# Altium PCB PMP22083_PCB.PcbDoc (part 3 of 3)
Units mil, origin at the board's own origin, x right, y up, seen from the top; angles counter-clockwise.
Board outline 6200 x 4200 mil, 2 copper layers (Top Layer, Bottom Layer), stack 62 mil thick; 186 components, 87 nets, 426 pads, 96 vias.
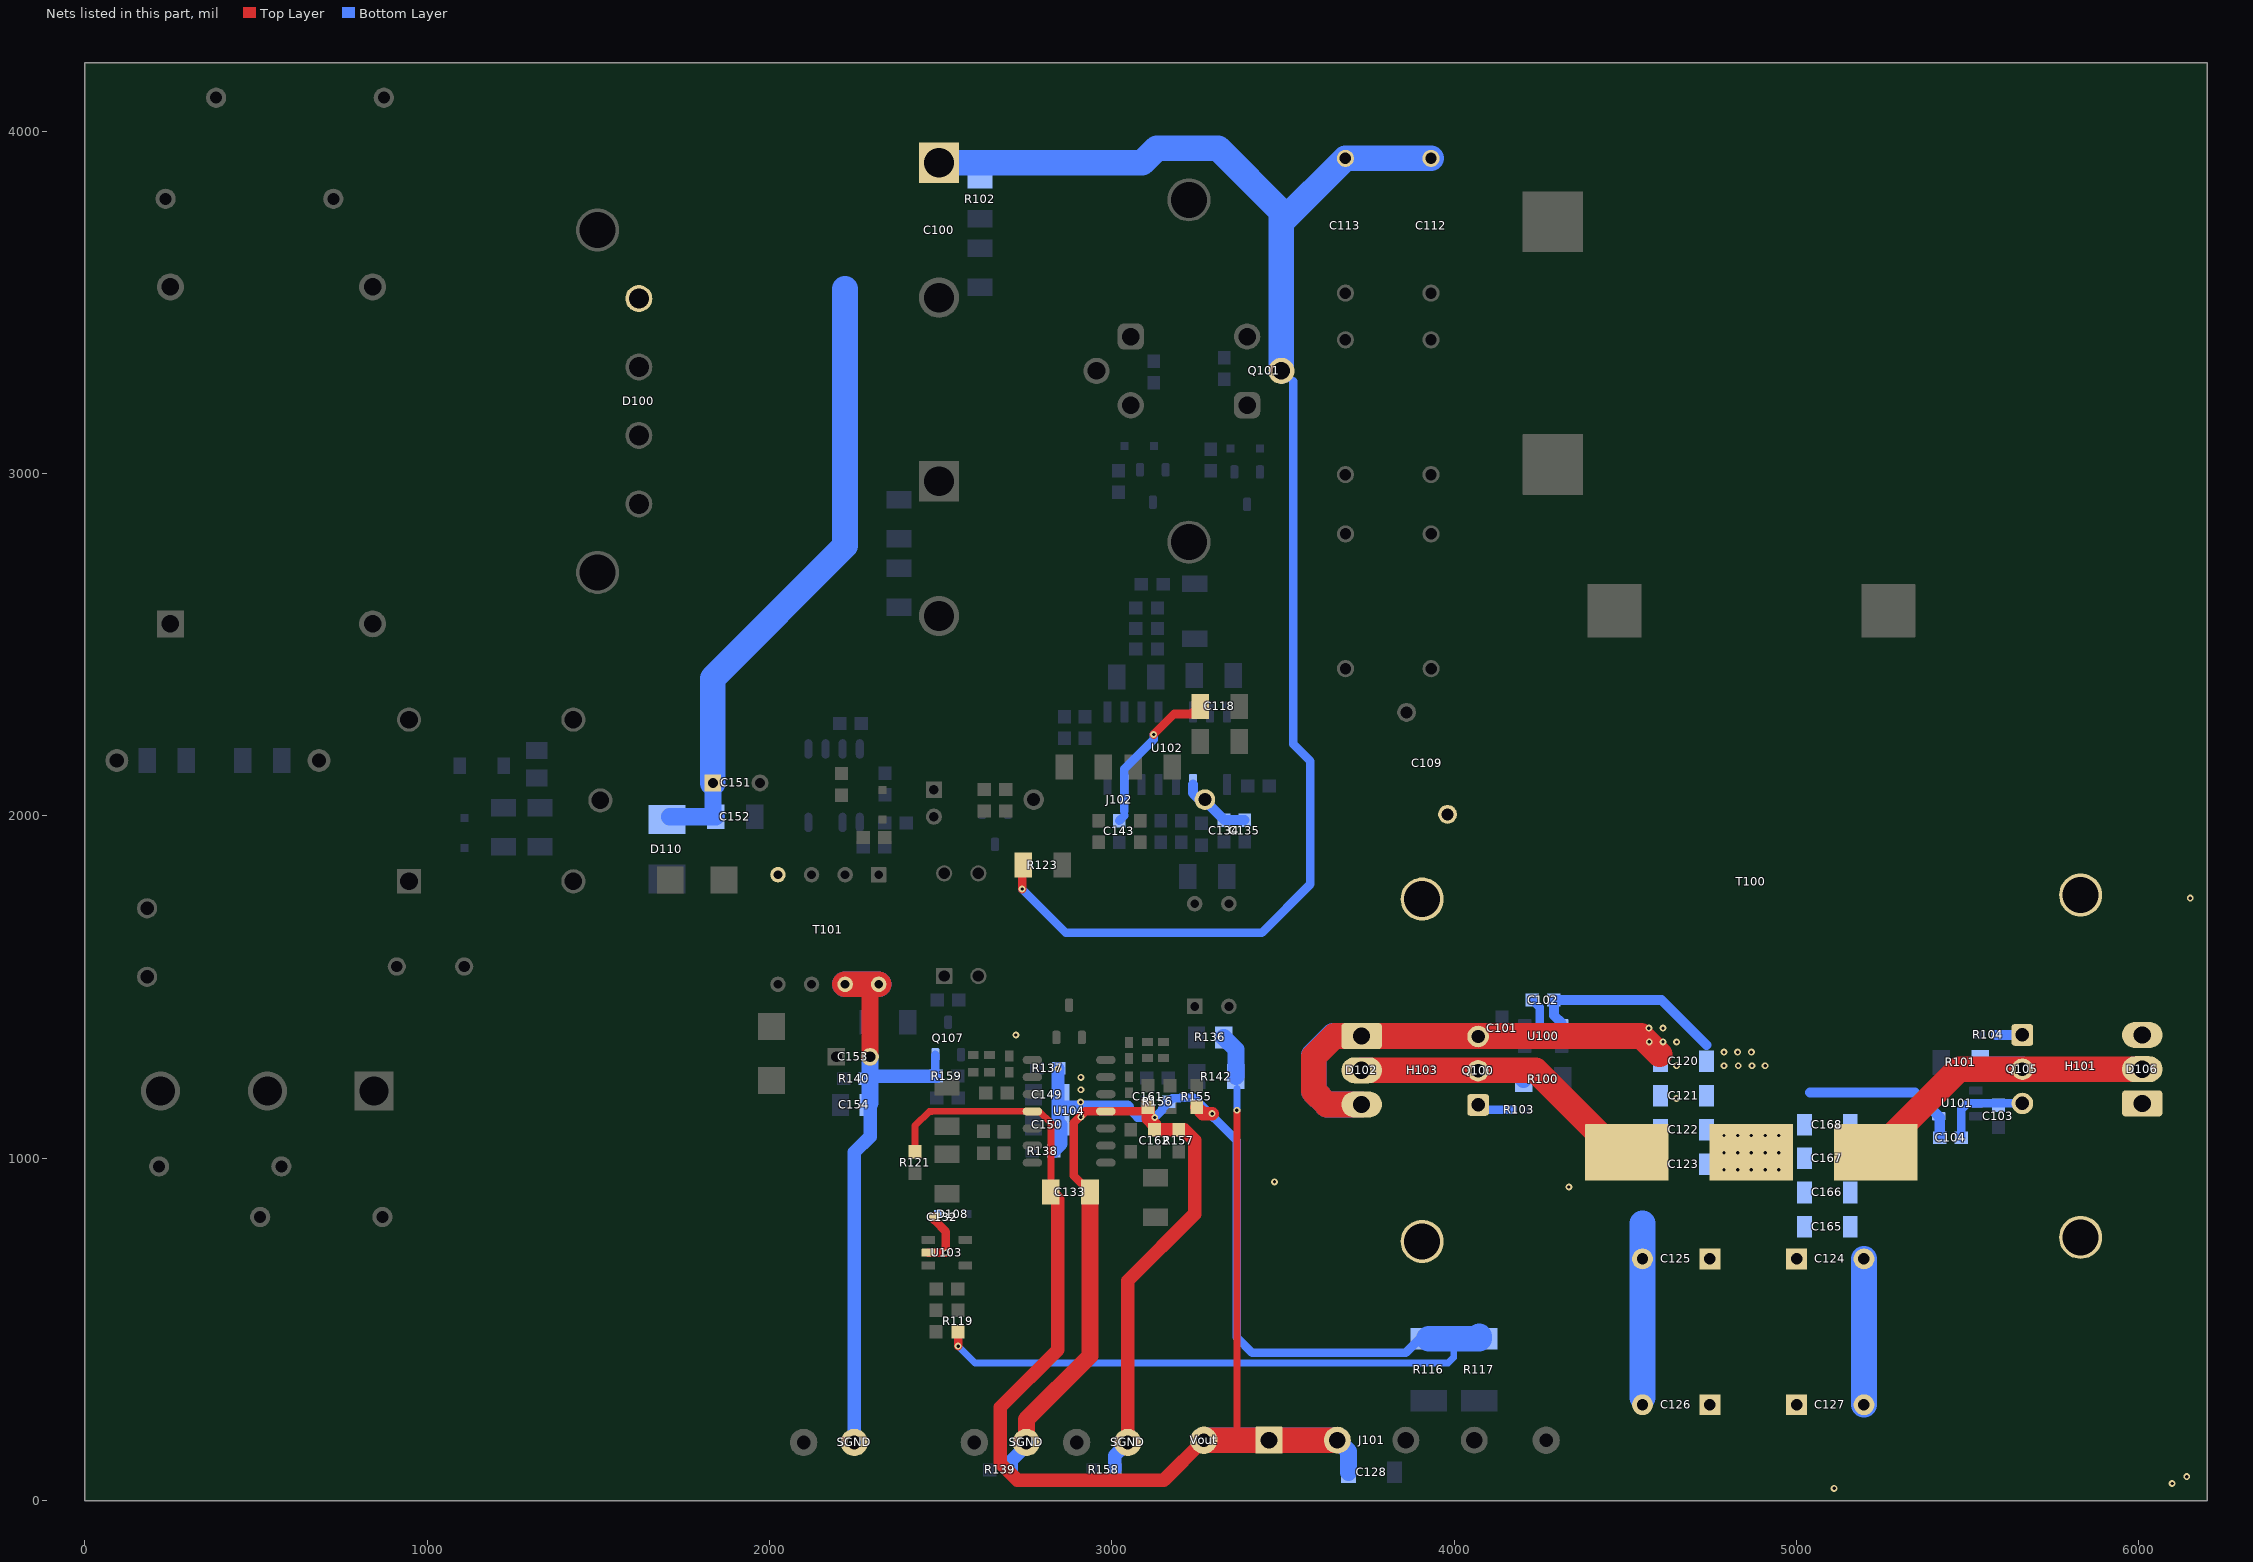
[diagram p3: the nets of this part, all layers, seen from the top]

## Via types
v1: diameter 20, hole 10, Top Layer to Bottom Layer, 96 vias

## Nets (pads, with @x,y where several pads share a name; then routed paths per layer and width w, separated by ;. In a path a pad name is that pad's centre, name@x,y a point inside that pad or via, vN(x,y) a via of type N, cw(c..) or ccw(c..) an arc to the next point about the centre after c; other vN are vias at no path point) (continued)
SGND: C101.2 C102.2 C103.2 C104.2 C109.1 C120.2 C121.2 C122.2 C123.2 C124.2 C125.2 C126.2 C127.2 C132.2 C133.1 C149.2 C150.2 C153.2 C154.2 C161.2 C162.2 C165.1 C166.1 C167.1 C168.1 D102.1 D102.3 D106.1 D106.3 D108.2 H101.1 H101.2 H103.1 H103.2 Q100.3 Q105.3 Q107.2 R116.1 R117.1 R119.2 R137.1 R138.1 R139.1 R140.1 R155.1 R156.1 R157.1 R158.1 R159.1 SGND.1@2248,169.78 SGND.1@2750.42,169.78 SGND.1@3046.72,169.78 T101.7 T101.8 U100.2 U101.2 U103.2 U104.11 | length 11895.4
  Top Layer w25: U103.2@2464.27,724.13 v1(2515.47,724.13) 2515.47,785.55 2481.85,819.17 C132.2@2481.85,828.3 ; v1(2551.22,451.06) R119.2@2551.22,492.95 ; C133.1@2936.41,901.06 2888.34,949.13 2888.34,1102.9 2922.4,1136.96 U104.11@2982.75,1136.96 C161.2@3094.69,1136.96
  Top Layer w39.37: SGND.1@3046.72,169.78 3046.72,641.92 3241.73,836.92 3241.73,1052.72 3211.89,1082.56 R157.1@3195.47,1082.56 C162.2@3124.92,1082.56 3124.92,1097.17 3106.22,1115.87 C161.2@3106.22,1148.49 ; R155.1@3248.38,1148.49 3266.41,1130.45 v1(3292.99,1130.45)
  Top Layer w50: C153.2@2294.17,1296.33 2294.17,1483.22 ; SGND.1@2750.42,169.78 2750.42,236.57 2936.41,422.56 C133.1@2936.41,901.06
  Top Layer w75: T101.7@2221.06,1508.11 T101.8@2319.06,1508.11 ; D102.3@3730,1156.91 3628.53,1156.91 3590,1195.44 3590,1296.91 3650,1356.91 D102.1@3730,1356.91 4546.56,1356.91 4600,1303.48
  Bottom Layer w20: v1(2551.22,451.06) 2600.25,402.04 3982.67,402.04 3998.84,418.21 3998.84,463.17 4008.26,472.59
  Bottom Layer w25: R159.1@2484.74,1242.29 Q107.2@2484.74,1302.76 ; 3045.47,1148.49 3075,1118.96 v1(3125.47,1118.96) 3147.25,1140.74 3147.25,1145.73 R156.1@3166.26,1164.74 3176.43,1174.91 3197.89,1174.91 3199.76,1176.78 3239.76,1176.78 3365.47,1051.06 3365.47,476.57 3410,432.04 3858.84,432.04 R116.1@3899.39,472.59 ; Q100.3@4071.19,1356.78 U100.2@4205.87,1356.78 4206.44,1357.35 4237.19,1357.35 4250,1370.16 4250,1440.46 C102.2@4228.5,1461.96 ; C104.2@5481.5,1060 5481.5,1142.56 5498.94,1160 U101.2@5524.13,1160 Q105.3@5660,1160
  Bottom Layer w39.37: SGND.1@2248,169.78 2248,1017.22 2294.17,1063.39 C154.2@2294.17,1161.82 ; R140.1@2294.17,1240 R159.1@2487.03,1240 ; R139.1@2706.24,89.78 2706.24,116.24 SGND.1@2750.42,160.42 ; R138.1@2830.13,1021.06 2851.49,1042.42 C150.2@2851.49,1097.59 ; C150.2@2842.99,1106.09 v1(2842.99,1261.2) ; 2846.04,1148.49 3045.47,1148.49 ; R158.1@3008.16,90 3008.16,131.22 SGND.1@3046.72,169.78
  Bottom Layer w50: C154.2@2294.17,1161.82 2294.17,1240 C153.2@2294.17,1296.33
  Bottom Layer w75: T101.7@2221.06,1508.11 T101.8@2319.06,1508.11 ; D102.3@3730,1156.91 3628.53,1156.91 3590,1195.44 3590,1300 3646.91,1356.91 D102.1@3730,1356.91 Q100.3@4068.68,1356.91 ; R116.1@3925.58,472.59 4008.26,472.59 R117.1@4073.22,472.59 R117.1@4073.22,479.25 ; C126.2@4550,300 4550,810 ; C127.2@5197.13,280 C124.2@5197.13,706.07
  other v1: 5110,35.58 6097,50 6140,70 4335.39,916.06 3475.37,931.06 2910,1120 2909.11,1163.78 4650,1174.71 2910,1200 2910,1236.26 4650,1270 4570,1340 4610,1340 4650,1339.5 2720,1360 4568.88,1380 4610,1380 6150,1760
Vbus: C100.1 C112.1 C113.1 C151.1 C152.1 D100.1 D110.2 Q101.2 R102.2 R123.2 T101.4 | length 6416.2
  Top Layer w25: v1(2738.22,1786.33) R123.2@2738.22,1853.41
  Bottom Layer w25: T101.4@2025.06,1828.11 T101.4@2027.06,1826.11 ; v1(2738.22,1786.33) 2866.22,1658.32 3438.32,1658.32 3580,1800 3580,2160 3530,2210 3530,3270
  Bottom Layer w50: D110.2@1708.72,1997.49 C152.1@1843.43,1997.49 ; C152.1@1834.69,2006.23 C151.1@1834.69,2096.22
  Bottom Layer w75: C151.1@1834.69,2096.22 1834.69,2402.36 2221.06,2788.73 2221.06,3539.24 ; C100.1@2495.39,3907.57 3089.47,3907.57 3131.81,3949.91 3311.07,3949.91 3495.43,3765.56 3495.43,3733.54 ; Q101.2@3495.43,3299.74 3495.43,3733.54 ; C112.1@3932.48,3920.59 C113.1@3682.48,3920.59 3495.43,3733.54
VCC: C134.2 C135.2 J102.2 U102.3 | length 208.7
  Bottom Layer w29.53: U102.3@3237.08,2091.33 3237.08,2066.33 3255.78,2047.63 3268.41,2047.63 C134.2@3328.22,1987.82 C135.2@3388.22,1987.82
VCR: C118.2 C143.1 U102.7 | length 456.8
  Top Layer w25: v1(3122.08,2237.63) 3182.08,2297.63 3231.68,2297.63 C118.2@3261.68,2327.63
  Bottom Layer w25: C143.1@3022.08,1986.02 C143.1@3037.08,2001.02 ; 3037.08,2014.14 U102.7@3037.08,2091.33 3037.08,2137.63 3122.08,2222.63 v1(3122.08,2237.63)
VD_SR1: D102.2 Q100.2 R100.1 T100.6 | length 920.7
  Top Layer w75: D102.2@3730,1256.91 4237.63,1256.91 T100.6@4428.22,1066.33
  Bottom Layer w50: Q100.2@4070,1255.59 4177.32,1255.59 R100.1@4202.91,1230
VD_SR2: D106.2 Q105.2 R101.1 T100.8 | length 981.8
  Top Layer w75: T100.8@5231.61,1017.35 5474.26,1260 Q105.2@5660,1260 D106.2@6010,1260
  Bottom Layer w75: R101.1@5557.09,1260 Q105.2@5660,1260
VG_SR1: Q100.1 R103.1 | length 81.8
  Bottom Layer w25: Q100.1@4084.53,1141.06 R103.1@4166.38,1141.06
VG_SR2: Q105.1 R104.1 | length 76.4
  Bottom Layer w29.53: R104.1@5583.62,1360 Q105.1@5660,1360
Vout: C102.1 C104.1 C120.1 C121.1 C122.1 C123.1 C124.1 C125.1 C126.1 C127.1 C128.1 C133.2 C165.2 C166.2 C167.2 C168.2 J101.1 J101.2 R121.2 R136.2 R142.2 T100.7 U100.4 U101.4 U104.4 Vout.1 | length 5321
  Top Layer w20: R121.2@2425.47,1018.45 2425.47,1095.47 2466.96,1136.96 2474.08,1136.96 2474.56,1137.44 2768.19,1137.44 U104.4@2768.19,1136.96 2788.19,1136.96 2822.24,1102.9 C133.2@2822.24,901.06 ; 3365.47,180.97 v1(3365.47,1139.94)
  Top Layer w39.37: C133.2@2822.24,901.06 2842.71,880.59 2842.71,440.7 2674.75,272.73 2674.75,108.92 2723.66,60 3152.4,60 Vout.1@3268.84,176.44
  Top Layer w75: Vout.1@3268.84,176.44 J101.1@3458.84,176.44 J101.2@3658.84,176.44
  Bottom Layer w20: v1(3365.47,1139.94) R142.2@3365.47,1203.41
  Bottom Layer w29.53: U100.4@4314.13,1394.18 4291.5,1416.82 C102.1@4291.5,1461.96 4605.8,1461.96 4736.93,1330.83 ; 5040,1192.01 5346.45,1192.01 U101.4@5415.87,1122.6 ; C104.1@5418.5,1060 U101.4@5418.5,1119.96
  Bottom Layer w50: R136.2@3327.08,1352.76 3362.56,1317.28 R142.2@3362.56,1238.23 ; J101.2@3658.84,176.44 3691.91,143.37 C128.1@3691.91,82.62
  Bottom Layer w75: Vout.1@3268.84,176.44 J101.1@3458.84,176.44 J101.2@3658.84,176.44
  other v1: 4788.22,966.33 4828.22,966.33 4868.22,966.33 4908.22,966.33 4948.22,966.33 4788.22,1016.33 4828.22,1016.33 4868.22,1016.33 4908.22,1016.33 4948.22,1016.33 4788.22,1066.33 4828.22,1066.33 4868.22,1066.33 4908.22,1066.33 4948.22,1066.33 4788.22,1270 4830,1270 4870,1270 4908.22,1270 4788.22,1310 4828.22,1310 4868.22,1310

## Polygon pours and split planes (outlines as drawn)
NetC107_2 on Bottom Layer "C107_2" (solid, pour order 134): 60.71,2610 10.71,2560 10.71,1710 40.71,1680 210.71,1680 230.71,1700 230.71,2406.33 300.71,2476.33 300.71,2580.03 270.74,2610
NetC105_2 on Bottom Layer "C105_2" (solid, pour order 132): 110,950 10,1050 10,1550 40,1580 210,1580 230,1560 230,1289.5 280,1239.5 280,996.5 233.5,950
NetC100_2 on Bottom Layer "C100_2" (solid, pour order 124): 810,2511.19 790,2531.19 790,2897.52 1053.67,3161.19 1649.13,3161.19 1669.13,3141.19 1669.13,3082.5 1647.82,3061.19 1471.67,3061.19 921.67,2511.19
NetC111_1 on Bottom Layer "C111_1" (solid, pour order 118): 700,3830 690,3820 690,3790 800,3680 800,3510.02 1050.02,3260 1639.13,3260 1669.13,3290 1669.13,3335.43 1644.56,3360 1479.76,3360 1009.76,3830
NetC107_1 on Bottom Layer "C107_1" (solid, pour order 116): 720,1459.42 720,1460 620,1560 620,2220.14 460,2380.14 460,2698.37 100,3058.37 100,3580 130,3610 290,3610 310,3590 310,3100 610,2800 610,2492.5 752.5,2350 970,2350 1000,2320 1000,2260.03 873.82,2133.84 873.82,1719.44 964.35,1628.91 964.35,1499.58 924.18,1459.42
NetC110_1 on Bottom Layer "C110_1" (solid, pour order 114): 1267.69,1740 1157.11,1850.58 1098.88,1850 897.79,1850 886.85,1839.05 886.85,1722.84 979.69,1630 979.69,1500 779.69,1300 779.69,1139.94 839.69,1079.94 839.69,812.77 859.69,792.77 859.69,790 899.69,790 1267.69,1158
Vout on Bottom Layer "Vout" (solid, pour order 108): 3700,18.96 3720,38.96 3720,291.91 3691.91,320 3321.08,320 3214.17,213.08 3214.17,85.83 3280,20
SGND on Bottom Layer "SGND" (solid, pour order 106): 2752.25,1383.47 2491.51,1383.47 2337.46,1540.37 2200,1540 2190,1530 2190,30.52 2210.52,10 3150,10 3170,30 3170,330 3150,350 2548.18,350 2466.96,431.22 2466.96,461.4 2475.55,470 2566.22,470 2613.66,422.56 3888.46,422.56 3910,444.1 3910,518.2 3888.2,540 3442.08,540 3442.08,1003.41 3194.48,1251.01 3190.87,1254.62 2996.59,1254.62 2964.25,1289.61 2846.12,1289.61
Vout on Bottom Layer "Vout" (solid, pour order 94): 4720,660 4700,680 4700,1319.23 4720,1339.23 4720.15,1339.08 4916.36,1339.08 5070,1185.44 5070,679.2 5050.8,660
SGND on Bottom Layer "SGND" (solid, pour order 102): 5660,2030 5557.09,1927.09 5557.09,1288.56 5435.83,1167.3 4842.2,1167.3 4602.59,1406.91 4289.31,1406.91 4176.22,1520 4176.22,1987.6 4137.5,2030 3845.86,2030 3830,2014.14 3830,1660 3458.84,1288.84 3458.84,492.22 3500,451.06 3848.94,451.06 3880,420 3980,420 4050,350 4308.84,350 4340,318.84 4340,40 4360,20 6160,20 6190,50 6190,1770 5930,2030
PGND on Bottom Layer "Bottom Layer-PGND 1" (solid, pour order 88): 3968.22,3116.33 3998.22,3086.33 3998.22,2987.65 3957.33,2946.76 3921.61,2946.76 3650.86,2946.76 3609.97,2987.65 3609.97,3088.08 3638.22,3116.33
PGND on Bottom Layer "Bottom Layer-PGND" (solid, pour order 86): 3131.55,2717.45 3098.22,2750.78 3098.22,2856.01 3128.22,2886.01 3277.55,2886.01 3304.2,2859.35 3304.2,2751.19 3270.47,2717.45
NetC128_2 on Bottom Layer "C124_2" (solid, pour order 76): 3798.84,62.04 3818.84,42.04 4258.84,42.04 4328.84,112.04 4328.84,317.04 4303.84,342.04 3849.67,342.04 3799.11,291.49
PGND on Bottom Layer "PGND" (solid, pour order 56): 2698.86,2595.7 2689.49,2586.33 2610.53,2586.33 2610.9,2505.95 2581.86,2476.33 2508.22,2476.33 2498.22,2486.33 2456.9,2486.33 2436.9,2506.33 2436.9,2645 2475.14,2683.25 2475.14,2856.33 2560.52,2856.32 2618.22,2914.03 2618.22,3016.33 2618.65,3016.76 2618.65,3390.59 2624.35,3390.59 2701.8,3468.04 2701.8,3609.91 2988.22,3896.33 3278.22,3896.33 3308.22,3866.33 3308.22,3726.33 3218.22,3636.32 2958.22,3636.33 2838.22,3516.33 2838.22,3296.32 2918.22,3216.32 3008.22,3216.33 3038.22,3246.33 3142.54,3246.33 3100.88,3204.67 3100.88,3176.3 3074.44,3150.34 3045.15,3150.34 3045.15,3147.48 2982.13,3084.46 2982.13,2746.87 2929.3,2694.03 2929.3,2636.32 2738.68,2636.32
PGND on Bottom Layer "PGND" (solid, pour order 54): 2508.22,2576.33 2508.22,2231.54 2583.44,2156.33 2611.89,2156.33 2611.89,2104.26 2959.83,1756.33 3373.63,1756.33 3478.22,1860.91 3478.22,2075.95 3448.22,2105.95 3206.15,2105.95 3098.22,2213.88 3098.22,2608.53 3080.42,2626.33 2746.59,2626.33 2696.59,2576.33
NetC112_2 on Bottom Layer "C112_2" (solid, pour order 28): 3668.22,3556.33 3648.22,3536.33 3648.22,3376.33 3668.22,3356.33 3948.53,3356.33 3968.53,3376.33 3968.22,3376.64 3968.22,3536.33 3948.22,3556.33
PGND on Bottom Layer "PGND" (solid, pour order 58): 2488.22,2546.33 2488.22,2046.33 2508.22,2026.33 2508.22,1902.49 2402.06,1796.33 2298.22,1796.33 2298.22,1856.33 2328.22,1856.33 2328.22,1892.76 2171.82,2049.16 2171.82,2137.49 2215.26,2180.93 2262.69,2180.93 2263.98,2179.65 2298.22,2213.89 2298.22,2366.33 2408.22,2476.33 2408.22,2547.57 2399.47,2556.33
PGND on Bottom Layer "PGND" (solid, pour order 44): 1938.22,1966.33 1928.22,1976.33 1928.22,2347.82 2216.72,2636.33 2485.39,2636.33 2498.22,2623.49 2498.22,2575.08 2228.22,2305.08 2228.22,2162.73 2171.82,2106.33 2113.88,2106.33 2018.22,2010.67 2018.22,1976.33 2008.22,1966.33
NetD112_2 on Bottom Layer "D108_2" (solid, pour order 24): 2088.22,1996.33 2098.23,2006.33 2098.23,2007.4 2117.14,2007.4 2128.22,1996.33 2128.22,1946.87 2158.22,1916.87 2158.22,1806.33 2138.22,1786.33 2108.34,1786.33 2088.22,1806.45
Vbus on Bottom Layer "Vbus" (solid, pour order 22): 2058.22,1846.33 2038.22,1866.33 1963.95,1866.33 1867.84,1962.44 1867.84,2036.71 1878.22,2047.09 1878.22,2135.95 1867.84,2146.33 1647.82,2146.33 1628.22,2126.73 1628.22,1956.33 1638.22,1946.33 1740.96,1946.33 1900.96,1786.33 2046.43,1786.33 2058.22,1798.11
Vbus on Bottom Layer "Vbus" (solid, pour order 20): 1588.24,3466.33 1568.24,3486.33 1568.22,3486.33 1568.22,3576.33 2138.22,4146.33 3988.22,4146.33 4018.22,4116.33 4018.22,3916.33 3978.22,3876.33 3828.22,3876.33 3578.22,3626.33 3578.22,3288.57 3545.98,3256.33 3484.49,3256.33 3454.49,3286.33 3454.49,3317.04 3468.22,3330.77 3468.22,3696.33 3278.22,3886.33 3171.24,3886.33 3132.88,3847.97 2569.86,3847.97 2188.22,3466.33
NetD110_1 on Bottom Layer "D110_1" (solid, pour order 90): 1636.28,1898.89 1626.28,1888.89 1626.28,1778.89 1646.28,1758.89 1746.28,1758.89 1756.28,1768.89 1756.28,1890.49 1747.3,1899.47
NetC107_1 on Top Layer "C107_1" (solid, pour order 138): 749.86,2350 620,2220.14 620,1560 720,1460 720,1459.42 924.18,1459.42 964.35,1499.58 964.35,1628.91 873.82,1719.44 873.82,2133.84 1000,2260.03 1000,2320 970,2350
NetC105_2 on Top Layer "C105_2" (solid, pour order 130): 110,950 10,1050 10,1550 40,1580 210,1580 230,1560 230,1289.5 280,1239.5 280,996.5 233.5,950
NetC107_2 on Top Layer "C107_2" (solid, pour order 128): 60,2610 10,2560 10,1710 40,1680 210,1680 230,1700 230,2406.33 300,2476.33 300,2580.03 270.03,2610
PE on Top Layer "PE" (solid, pour order 126): 330,4070 310,4090 310,4170 330,4190 910,4190 930,4170 930,4090 910,4070
NetC100_2 on Top Layer "C100_2" (solid, pour order 122): 810,2510 790,2530 790,2896.33 1053.67,3160 1649.13,3160 1669.13,3140 1669.13,3081.31 1647.82,3060 1471.67,3060 921.67,2510
NetC111_1 on Top Layer "C111_1" (solid, pour order 120): 700,3830 690,3820 690,3790 800,3680 800,3510 1050,3260 1639.13,3260 1669.13,3290 1669.13,3335.43 1644.56,3360 1479.76,3360 1009.76,3830
NetC110_1 on Top Layer "C110_1" (solid, pour order 112): 860,790 860,792.77 840,812.77 840,1079.94 780,1139.94 780,1300 980,1500 980,1630 887.16,1722.84 887.16,2013.11 1010,2135.95 1514.05,2135.95 1540,2110 1540,1991.86 1528.97,1980.83 1330.71,1980.83 1268,1918.12 1268,1158 900,790
SGND on Top Layer "SGND" (solid, pour order 110): 2861.13,1421.05 2898.71,1383.47 2906.72,1383.47 2906.72,1368.69 3084.82,1190.59 3249.9,1194.08 3346.69,1097.29 3346.69,836.78 3330.98,821.06 2859.64,821.06 2832.08,848.62 2832.08,1105.24 2707.33,1230 2262.15,1230 2190,1302.15 2190,1530 2200,1540 2337.83,1540 2456.78,1421.05
SGND on Top Layer "SGND" (solid, pour order 104): 5660,2030 5557.09,1927.09 5557.09,1288.56 5435.83,1167.3 4842.2,1167.3 4602.59,1406.91 4289.31,1406.91 4176.22,1520 4176.22,1987.6 4137.5,2030 3845.86,2030 3830,2014.14 3830,1660 3458.84,1288.84 3458.84,921.16 3960,420 3980,420 4050,350 4308.84,350 4340,318.84 4340,40 4360,20 6160,20 6190,50 6190,1770 5930,2030
VD_SR2 on Top Layer "VD_SR2" (solid, pour order 100): 5120,920 5100,940 5100,1130 5270,1300 5686.96,1300 5700,1286.96 5700,1230 5690,1220 5640,1220 5340,920
VD_SR1 on Top Layer "VD_SR1" (solid, pour order 98): 4010,1220 4000,1230 4000,1282.5 4007.5,1290 4480,1290 4640,1130 4640,940 4620,920 4391.98,920 4091.98,1220
Vout on Top Layer "Vout" (solid, pour order 96): 4679.61,1289.61 4679.61,919.61 4640,880 4218.08,880 3980,640 3715.43,640 3395.43,320 3320.83,320 3310,309.17 3310,30 3320,20 5040,20 5070,50 5070,1160 4890,1340 4730,1340
PGND on Top Layer "PGND" (solid, pour order 52): 2896.27,1819.89 2896.27,1928.88 2888.22,1936.93 2888.22,2045.02 2836.92,2096.33 2671.89,2096.33 2611.89,2156.33 2583.44,2156.33 2508.22,2231.54 2508.22,2576.33 2696.59,2576.33 2746.59,2626.33 3080.42,2626.33 3098.22,2608.53 3098.22,2213.88 3206.15,2105.95 3448.22,2105.95 3478.22,2075.95 3478.22,1860.91 3373.63,1756.33 2959.83,1756.33
PGND on Top Layer "PGND" (solid, pour order 40): 2691.84,2588.54 2689.63,2586.33 2598.22,2586.33 2598.22,2489.11 2581.86,2476.33 2508.22,2476.33 2498.22,2486.33 2548.22,2856.33 2618.22,2926.33 2618.22,3016.33 2618.65,3016.76 2618.65,3806.76 2708.22,3896.33 3278.22,3896.33 3308.22,3866.33 3308.22,3726.33 3278.22,3696.33 2898.22,3696.33 2767.02,3565.13 2767.02,3277.52 2828.22,3216.33 3008.22,3216.33 3038.22,3246.33 3208.22,3246.33 3338.22,3116.33 3968.22,3116.33 3998.22,3086.33 3998.22,2986.33 3958.22,2946.33 3668.22,2946.33 3358.22,2636.33 2738.68,2636.32
HS on Top Layer "HS" (solid, pour order 38): 2996.38,3264.99 2987.71,3256.33 2888.22,3256.33 2838.22,3306.33 2838.22,3516.33 2948.22,3626.33 3425.43,3626.33 3625.43,3826.32 4378.22,3826.33 4388.22,3816.33 4388.22,3656.33 4378.22,3646.33 3695.43,3646.33 3405.43,3356.33 3319.77,3356.32 3199.77,3476.32 3005.43,3476.33 2975.43,3446.33 2975.43,3347.27 2996.38,3326.33
NetC114_1 on Top Layer "C116_1" (solid, pour order 32): 4388.22,2846.33 4548.22,2686.33 4548.22,2517.63 4516.92,2486.33 4348.22,2486.33 4218.22,2486.32 4068.22,2636.32 3718.22,2636.33 3638.22,2716.33 3638.22,2846.33 3688.22,2896.33 3978.22,2896.33 4208.22,3126.33 4368.22,3126.33 4388.22,3106.33
NetC112_2 on Top Layer "C112_2" (solid, pour order 30): 3668.22,3566.33 3648.22,3546.33 3648.22,3376.33 3668.22,3356.33 4488.22,3356.32 5118.22,2726.32 5118.22,2603.41 4944.74,2429.93 4194.62,2429.93 4078.22,2546.33 3708.22,2546.33 3648.22,2486.33 3648.22,2376.33 3668.22,2356.33 3986.72,2356.32 4096.72,2246.33 5068.22,2246.32 5348.22,2526.33 5348.22,2833.41 4615.31,3566.33
PGND on Top Layer "PGND" (solid, pour order 48): 2508.22,2026.33 2638.22,1896.32 2638.22,1820.35 2628.22,1810.35 2416.08,1810.35 2402.06,1796.33 2298.22,1796.33 2298.22,1856.33 2328.22,1856.33 2328.22,1892.76 2171.82,2049.16 2171.82,2137.49 2215.26,2180.93 2262.69,2180.93 2263.98,2179.65 2298.22,2213.89 2298.22,2366.33 2408.22,2476.33 2408.22,2547.57 2399.47,2556.33 2488.22,2546.33 2488.22,2046.33
PGND on Top Layer "PGND" (solid, pour order 42): 1951.21,2064.63 1928.22,2087.63 1928.22,2349.49 2215.06,2636.32 2485.39,2636.33 2498.22,2623.49 2498.22,2575.08 2228.22,2305.08 2228.22,2162.73 2171.82,2106.33 2113.88,2106.33 2072.19,2064.63
PGND on Top Layer "PGND" (solid, pour order 46): 1588.22,2956.33 1438.22,2806.33 1438.22,2586.33 1538.22,2486.33 2498.22,2486.33 2558.22,2546.33 2558.22,2846.33 2548.22,2856.33 2398.22,2856.33 2298.22,2956.33
NetC100_2 on Top Layer "C100_2" (solid, pour order 26): 1588.22,3066.33 2278.22,3066.33 2428.22,2916.33 2558.22,2916.33 2568.22,2926.33 2568.22,3546.33 2538.22,3576.33 2098.22,3576.32 1678.22,3156.32 1628.47,3156.33
NetD110_1 on Top Layer "D110_1" (solid, pour order 92): 1640,1893.78 1630,1883.78 1630,1773.78 1650,1753.78 1750,1753.78 1760,1763.78 1760,1885.38 1751.02,1894.35

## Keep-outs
Keep-Out Layer:
  text ".Layer_Name" at 577,-858.49 h60

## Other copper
Top Layer:
  text ".Layer_Name" at 577,-858.49 h60
Bottom Layer:
  text ".Layer_Name" at 577,-858.49 h60

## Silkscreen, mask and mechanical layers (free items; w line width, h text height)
Top Overlay:
  region: 1230.82,150 930.82,150 930.82,50 1230.82,50
  lines w10: 2585.47,851.06 2615.47,821.06 2615.47,784.13 2615.47,724.13 2615.47,681.06 ; 2678.45,1352.76 2678.45,1421.05 2775.17,1517.76 2775.17,1520 ; 2784.84,1728.5 2784.84,1727.66 ; 3020,740 3020,939.72 3046.6,966.33 ; 2784.84,1727.66 2758.99,1701.81 2758.99,1536.18 2785.17,1510 2810,1510 2966.43,1510 2990,1533.57 2990,1699.73 2962.08,1727.66 2784.84,1727.66 ; 2912.08,274.34 2912.08,713.82 2939.33,741.06 2940,741.06 2941.06,740 3130,740 3156.18,713.82 3160,713.82 3160,430 3160,310 3100,250 3020,250 2936.41,250 2912.08,274.34
  text "PMP22083RevC" at 151.41,66.33 h108.27
  text "0-5V" at 2624.66,53.73 h30
  text "0-5V" at 2919.92,53.95 h30
  text ".Layer_Name" at 577,-858.49 h60
Bottom Overlay:
  lines w10: 3040,1780 3040,1800.72 3074.24,1834.97 3074.24,1836.33 3074.24,1856.33 ; 2758.22,1626.33 2758.22,1756.33 2777.72,1775.82 3169.97,1775.82 3188.22,1757.58 3188.22,1756.33 3188.22,1626.3 3158.24,1596.33 2788.22,1596.33 2758.22,1626.33
  text ".Layer_Name" at 577,-858.49 h60
Top Paste:
  text ".Layer_Name" at 577,-858.49 h60
Bottom Paste:
  text ".Layer_Name" at 577,-858.49 h60
Top Solder:
  text ".Layer_Name" at 577,-858.49 h60
  text ".Layer_Name" at 577,-858.49 h60
Bottom Solder:
  text ".Layer_Name" at 577,-858.49 h60
Drill Guide:
  text ".Layer_Name" at 577,-858.49 h60
M1 Board Outline:
  lines w10: 4740,0 4750,0 ; 0,0 6200,0 6200,4200 0,4200 0,0
  text ".Layer_Name" at 577,-858.49 h60
M2 Board Dimensions:
  rectangle: 125,-400 500,-275
  rectangle: 0,-275 125,-150
  lines w7: 0,-275 1000,-275 ; 125,-400 125,-150 ; 250,-400 250,-150 ; 500,-400 500,-150 ; 750,-400 750,-150 ; 0,-400 0,-150 1000,-150 1000,-400 0,-400
  text ".Layer_Name" at 577,-858.49 h60
M3 3D STEP Top:
  text ".Layer_Name" at 577,-858.49 h60
M4 3D STEP Bottom:
  text ".Layer_Name" at 577,-858.49 h60
M5 Assembly Top:
  lines w10: -292,-930.17 6308,-930.17 ; -292,-726.83 6310,-726.83 ; -292,-523.5 -292,-1133.5 3713,-1133.5 6310,-1133.5 6310,-523.5 -291.5,-523.5 -291.5,-1133.5 1284,-1133.5 ; 2173,-1133.5 2173,-523.5 ; 3440,-726.83 3440,-523.5 ; 4280,-726.83 4280,-523.5 ; 4902,-1140 4902,-937.17
  text "COMPONENTS MARKED 'DNP' SHOULD NOT BE POPULATED." at 1153.5,-318.5 h60
  text "ASSEMBLY VARIANT:" at 1153,-434 h60
  text ".VariantName" at 2189,-434 h60
  text "PCB VIEWED FROM TOP SIDE" at -228.5,-655.67 h60
  text "BOARD #:" at 2248,-655.67 h60
  text ".PRJ_Number" at 2793.5,-655.67 h60
  text "REV:" at 3638,-655.67 h60
  text ".PCB_Rev" at 3929.5,-655.67 h60
  text "SVN REV:" at 4476,-655.67 h60
  text ".VersionControl_RevNumber" at 4982,-655.67 h60
  text "TID #:" at 2248,-859 h60
  text ".TID" at 2793.5,-859 h60
  text "PLOT NAME =" at -228.5,-1064.34 h60
  text ".plot_File_Name" at 577,-1064.34 h60
  text "GENERATED    :" at 2250,-1064.34 h60
  text ".Print_Date" at 3119.5,-1064.34 h60
  text ".Print_Time" at 3848.5,-1064.34 h60
  text "TEXAS INSTRUMENTS" at 5113,-1064.34 h60
M6 Assembly Bottom:
  lines w10: -292.5,-727.33 6309.5,-727.33 ; -290.5,-930.67 6309.5,-930.67 ; 1115.5,-1140.5 1115.5,-937.67 ; 1737.5,-727.33 1737.5,-524 ; 2577.5,-727.33 2577.5,-524 ; 3844.5,-1134 3844.5,-524 ; 4733.5,-1134 6309,-1134 6309,-524 -292.5,-524 -292.5,-1134 2304.5,-1134 6309.5,-1134 6309.5,-524
  text "COMPONENTS MARKED 'DNP' SHOULD NOT BE POPULATED." at 6102,-318 h60
  text ".VariantName" at 5058,-434 h60
  text "ASSEMBLY VARIANT:" at 6097,-434 h60
  text ".VersionControl_RevNumber" at 1035.5,-656.17 h60
  text "SVN REV:" at 1541.5,-656.17 h60
  text ".PCB_Rev" at 2088,-656.17 h60
  text "REV:" at 2379.5,-656.17 h60
  text ".PRJ_Number" at 3224,-656.17 h60
  text "BOARD #:" at 3769.5,-656.17 h60
  text "PCB VIEWED FROM BOTTOM SIDE" at 6246,-656.17 h60
  text ".TID" at 3224,-859.5 h60
  text "TID #:" at 3769.5,-859.5 h60
  text "TEXAS INSTRUMENTS" at 904.5,-1064.84 h60
  text ".Print_Time" at 2169,-1064.84 h60
  text ".Print_Date" at 2898,-1064.84 h60
  text "GENERATED    :" at 3767.5,-1064.84 h60
  text ".plot_File_Name" at 5440.5,-1064.84 h60
  text "PLOT NAME =" at 6246,-1064.84 h60
M9 Title Sheet:
  drawing of 57 lines, arcs and shapes, not listed
  text "1" at 739.84,8036.5 h70
  text "2" at 3235.5,8036.5 h70
  text "3" at 5724.84,8036.5 h70
  text "4" at 8231.51,8036.5 h70
  text "5" at 10730.5,8036.5 h70
  text "6" at 13235.5,8036.5 h70
  text "A" at -416.5,6893.5 h70
  text "A" at 14383.5,6893.5 h70
  text "B" at -416.5,4513.5 h70
  text "B" at 14383.5,4513.5 h70
  text "C" at -416.5,2138.5 h70
  text "C" at 14383.5,2138.5 h70
  text "PROJECT TITLE:" at 11343.5,277.5 h45
  text ".PRJ_Title" at 11393.5,144.17 h70
  text "DESIGNED FOR:" at 11343.5,-23.5 h45
  text ".PRJ_Customer" at 11393.5,-163.5 h70
  text "D" at -416.5,-231.5 h70
  text "D" at 14383.5,-231.5 h70
  text "FILE NAME:" at 11343.5,-323.5 h45
  text ".PCB_File_Name_No_Path" at 11393.5,-443.5 h70
  text "Texas Instruments (TI) and/or its licensors do not warrant the accuracy or completeness of this specification" at 6374,-605.34 h45
  text "ENGINEER:" at 11343.5,-613.5 h45
  text "LAYOUT BY:" at 12848.5,-613.5 h45
  text "or any information contained therein. TI and/or its licensors do not warrant that this design will meet" at 6329.01,-718 h45
  text ".PRJ_Engineer" at 11393.5,-768.49 h70
  text ".PCB_Layout" at 12899,-768.49 h70
  text "the specifications, will be suitable for your application or fit for any particular purpose, or will operate in" at 6329.01,-830.67 h45
  text ".Layer_Name" at 577,-858.49 h60
  text "ALTIUM DESIGNER VERSION:" at 12848.5,-923.5 h45
  text "an implementation. TI and/or its licensors do not warrant that the design is production worthy. You should" at 6329.01,-943.33 h45
  text "completely validate and test your design implementation to confirm the system functionality for your application." at 6374,-1056 h45
  text ".print_Scale" at 11393.5,-1056.83 h70
  text ".Application_BuildNumber" at 12899,-1056.83 h70
  text "1" at 739.84,-1263.5 h70
  text "2" at 3235.5,-1263.5 h70
  text "3" at 5724.84,-1263.5 h70
  text "4" at 8231.51,-1263.5 h70
  text "5" at 10730.5,-1263.5 h70
  text "6" at 13235.5,-1263.5 h70
M10 Fab Notes:
  drawing of 189 lines, arcs and shapes, not listed
  text "DESIGN INFORMATION" at 12382.02,6356.17 h60
  text "MIN. TRACK WIDTH:" at 11737.46,6224.05 h60
  text "8" at 12833.7,6224.05 h60
  text "MIL" at 12988.46,6224.05 h60
  text "MIN. CLEARANCE:" at 11737.46,6099.92 h60
  text "0.2" at 12773.7,6099.93 h60
  text "mm" at 12988.46,6099.92 h60
  text "MIN. VIA PAD SIZE:" at 11737.46,5975.8 h60
  text "20" at 12803.71,5975.8 h60
  text "MIL" at 12988.46,5975.8 h60
  text "0.05mm (2MIL)" at 12432.46,5845.9 h60
  text "MINIMUM ANNULAR RING" at 11408.23,5837.67 h60
  text "EXTERNAL" at 13140.46,5837.67 h60
  text "PER" at 11608.23,5727.55 h60
  text "IPC-D-275 CLASS 2 LEVEL C" at 11828.23,5727.54 h60
  text "MIL, HOLES" at 13316.46,5627.07 h60
  text "+/-" at 12924,5618.48 h60
  text "+/-" at 13778,5618.48 h60
  text "REGISTRATION TOLERANCES:" at 11408.23,5617.42 h60
  text "METAL" at 12608,5617.42 h60
  text "5" at 13184.2,5617.42 h60
  text "3" at 14017.2,5617.42 h60
  text "MIL" at 14133.46,5617.42 h60
  text "HOLE SIZE TOLERANCE (UNLESS OTHERWISE SPECIFIED):" at 11408.23,5519.1 h60
  text "+/-" at 13778,5516.23 h60
  text "3" at 14017.2,5515.17 h60
  text "MIL" at 14133.46,5515.17 h60
  text "MATERIAL:" at 11333.46,5377.52 h60
  text "FR-4 High Tg" at 12319.9,5249 h60
  text "X" at 12175.46,5241.01 h60
  text "FR-408" at 11754.46,5236.49 h60
  text "OTHER" at 13242.46,5236.49 h60
  text "62 MIL (1.6mm) +/-10%" at 12074.56,5093.46 h60
  text "X" at 11954.46,5091.01 h60
  text "THICKNESS:" at 11408.23,5085.24 h60
  text "OTHER" at 13359.46,5085.24 h60
  text "TOLERANCE:" at 11408.23,4946.92 h60
  text "X" at 12256.46,4946.92 h60
  text "ANSI IPC-6012 TYPE 3 CLASS 2" at 12434.48,4946.92 h60
  text "OTHER +/-" at 12434.46,4802.73 h60
  text "BOW & TWIST:" at 11408.23,4657.54 h60
  text "X" at 12256.46,4657.54 h60
  text "ANSI IPC-6012 TYPE 3 CLASS 2" at 12434.48,4657.54 h60
  text "OTHER +/-" at 12434.46,4510.85 h60
  text "DRILLING:" at 11333.46,4380.23 h60
  text "NC_DRILL FILES" at 13094.46,4275.04 h60
  text "REFERENCE:" at 11408.23,4271.1 h60
  text "X" at 12065.46,4271.01 h60
  text "AS SHOWN" at 12243.46,4271.1 h60
  text "X" at 12966.46,4271.1 h60
  text "OTHER" at 13392.46,4128.85 h60
  text "PTH COPPER THICKNESS:" at 11407.91,4125.32 h60
  text "X" at 12547.14,4125.32 h60
  text "20-30 um" at 12675.14,4125.32 h60
  text "BOARD FINISH:" at 11333.46,3977.73 h60
  text "SILKSCREEN:" at 11488.68,3867.6 h60
  text "X" at 12446.46,3867.6 h60
  text "TOP" at 12563.46,3867.6 h60
  text "X" at 12956.46,3867.6 h60
  text "BOTTOM" at 13074.46,3867.6 h60
  text "SILKSCREEN COLOR:" at 11488.68,3712.41 h60
  text "X" at 12445.46,3712.41 h60
  text "WHITE" at 12563.46,3712.41 h60
  text "OTHER" at 13074.46,3712.41 h60
  text "X" at 12576.46,3568.96 h60
  text "GREEN" at 12694.46,3568.96 h60
  text "OTHER" at 13312.46,3568.96 h60
  text "SOLDER RESIST COLOR:" at 11488.68,3562.1 h60
  text "X" at 12576.46,3414.71 h60
  text "MATTE" at 12694.46,3414.71 h60
  text "SEMI-GLOSS" at 13312,3414.07 h60
  text "IMMERSION GOLD (ENIG)" at 12394.46,3241.94 h60
  text "ENEPIG" at 13732,3234.72 h60
  text "SURFACE FINISH:" at 11333.46,3233.72 h60
  text "X" at 12216.46,3233.72 h60
  text "IMM. TIN/SILVER OR EQUIV" at 11663,3096.4 h60
  text "OTHER" at 13094.46,3092.47 h60
  text "ARRAY/PANEL:" at 11333.46,2937.09 h60
  text "CUT AND TRIM PER M1 BOARD OUTLINE" at 12394.46,2928.87 h60
  text "N.C. ROUTE" at 12394.46,2792.9 h60
  text "X" at 13082.46,2792.9 h60
  text "V. SCORE" at 13260.46,2792.9 h60
  text "CERTIFICATION:" at 11333.46,2663.77 h60
  text "MATERIALS AND WORKMANSHIP FOR ALL PCBS" at 12058.46,2663.77 h60
  text "TO MEET OR EXCEED THE REQUIREMENTS OF:" at 12058.46,2569.71 h60
  text "X" at 11695.97,2441.08 h60
  text "ANSI IPC-A-600F CLASS ->" at 11823.96,2441.08 h60
  text "X" at 13471.97,2441.08 h60
  text "2" at 13581.96,2441.08 h60
  text "1" at 13266.96,2439.58 h60
  text "3" at 13935.96,2439.58 h60
  text "X" at 12507.97,2293.39 h60
  text "RoHS" at 12635.96,2293.39 h60
  text "OTHER" at 13280.36,2293.39 h60
  text "PER ORDER" at 13677.42,2293.39 h60
  text "ALL BOARDS MUST MEET OR EXCEED UL94-V0 REQUIREMENTS." at 11361,2139.57 h60
  text "PCB MUST BEAR THE UL94V-0 UL REGISTERED MATERIAL ID NUMBER" at 11361,2023.5 h60
  text "ADDITIONAL REQUIREMENTS:" at 11333.46,1854.08 h60
  text "MICROSECTION:" at 11408.23,1746.95 h60
  text "YES" at 12313.96,1746.95 h60
  text "REQUIRED" at 13175.46,1602.62 h60
  text "BARE BOARD ELEC. TEST:" at 11408.23,1599.76 h60
  text "NONE" at 12713.96,1599.76 h60
  text "X" at 13057.46,1599.76 h60
  text "PER ORDER" at 13767.46,1599.76 h60
  text "XX MIL VIAS REQUIRE NON-CONDUCTIVE FILL AND PLANARIZE" at 11576.38,1394.82 h59
  text "XX MIL VIAS REQUIRE CONDUCTIVE FILL AND PLANARIZE" at 11584.38,1290.84 h60
  text "OUTER XX MIL TRACES REQUIRE 50 OHM SINGLE-ENDED IMPEDANCE" at 11583.39,1127.46 h58
  text "LAYER 2 & 3 (INNER LAYERS) XX MIL WIDE, XX MIL SPACE / TRACES REQUIRE 100 OHM DIFFERENTIAL IMPEDANCE" at 11575.39,891.74 h60
  text ".Layer_Name" at 577,-858.49 h60
M11 Gerber Information:
  lines w10: -292,-930.17 6308,-930.17 ; -292,-726.83 6310,-726.83 ; -292,-523.5 -292,-1133.5 3713,-1133.5 6310,-1133.5 6310,-523.5 -291.5,-523.5 -291.5,-1133.5 1284,-1133.5 ; 2173,-1133.5 2173,-523.5 ; 3440,-726.83 3440,-523.5 ; 4280,-726.83 4280,-523.5 ; 4902,-1140 4902,-937.17
  text "ALL ARTWORK VIEWED FROM TOP SIDE" at -228.5,-655.67 h60
  text "BOARD #:" at 2248,-655.67 h60
  text ".PRJ_Number" at 2793.5,-655.67 h60
  text "REV:" at 3638,-655.67 h60
  text ".PCB_Rev" at 3929.5,-655.67 h60
  text "SVN REV:" at 4476,-655.67 h60
  text ".VersionControl_RevNumber" at 4982,-655.67 h60
  text "LAYER NAME =" at -228.5,-858.49 h60
  text "TID #:" at 2248,-859 h60
  text ".TID" at 2793.5,-859 h60
  text "PLOT NAME =" at -228.5,-1064.34 h60
  text ".plot_File_Name" at 577,-1064.34 h60
  text "GENERATED    :" at 2250,-1064.34 h60
  text ".Print_Date" at 3119.5,-1064.34 h60
  text ".Print_Time" at 3848.5,-1064.34 h60
  text "TEXAS INSTRUMENTS" at 5113,-1064.34 h60
M12 Stackup:
  text ".Layer_Name" at 577,-858.49 h60
M13 Component Bodies Top:
  text ".Layer_Name" at 577,-858.49 h60
M14 Component Bodies Bottom:
  text ".Layer_Name" at 577,-858.49 h60
M15 Courtyards Top:
  text ".Layer_Name" at 577,-858.49 h60
M16 Courtyards Bottom:
  text ".Layer_Name" at 577,-858.49 h60
Drill Drawing:
  text ".Layer_Name" at 577,-858.49 h60
M17 Embedded Cavity:
  text ".Layer_Name" at 577,-858.49 h60
M18 Embedded Assembly:
  text ".Layer_Name" at 577,-858.49 h60
M19 Embedded Keepout:
  text ".Layer_Name" at 577,-858.49 h60

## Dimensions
0,0 to 6200,0 on M2 Board Dimensions
0,0 to 0,4200 on M2 Board Dimensions
0,-400 to 1000,-400 on M2 Board Dimensions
